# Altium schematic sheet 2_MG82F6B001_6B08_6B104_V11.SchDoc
size A4
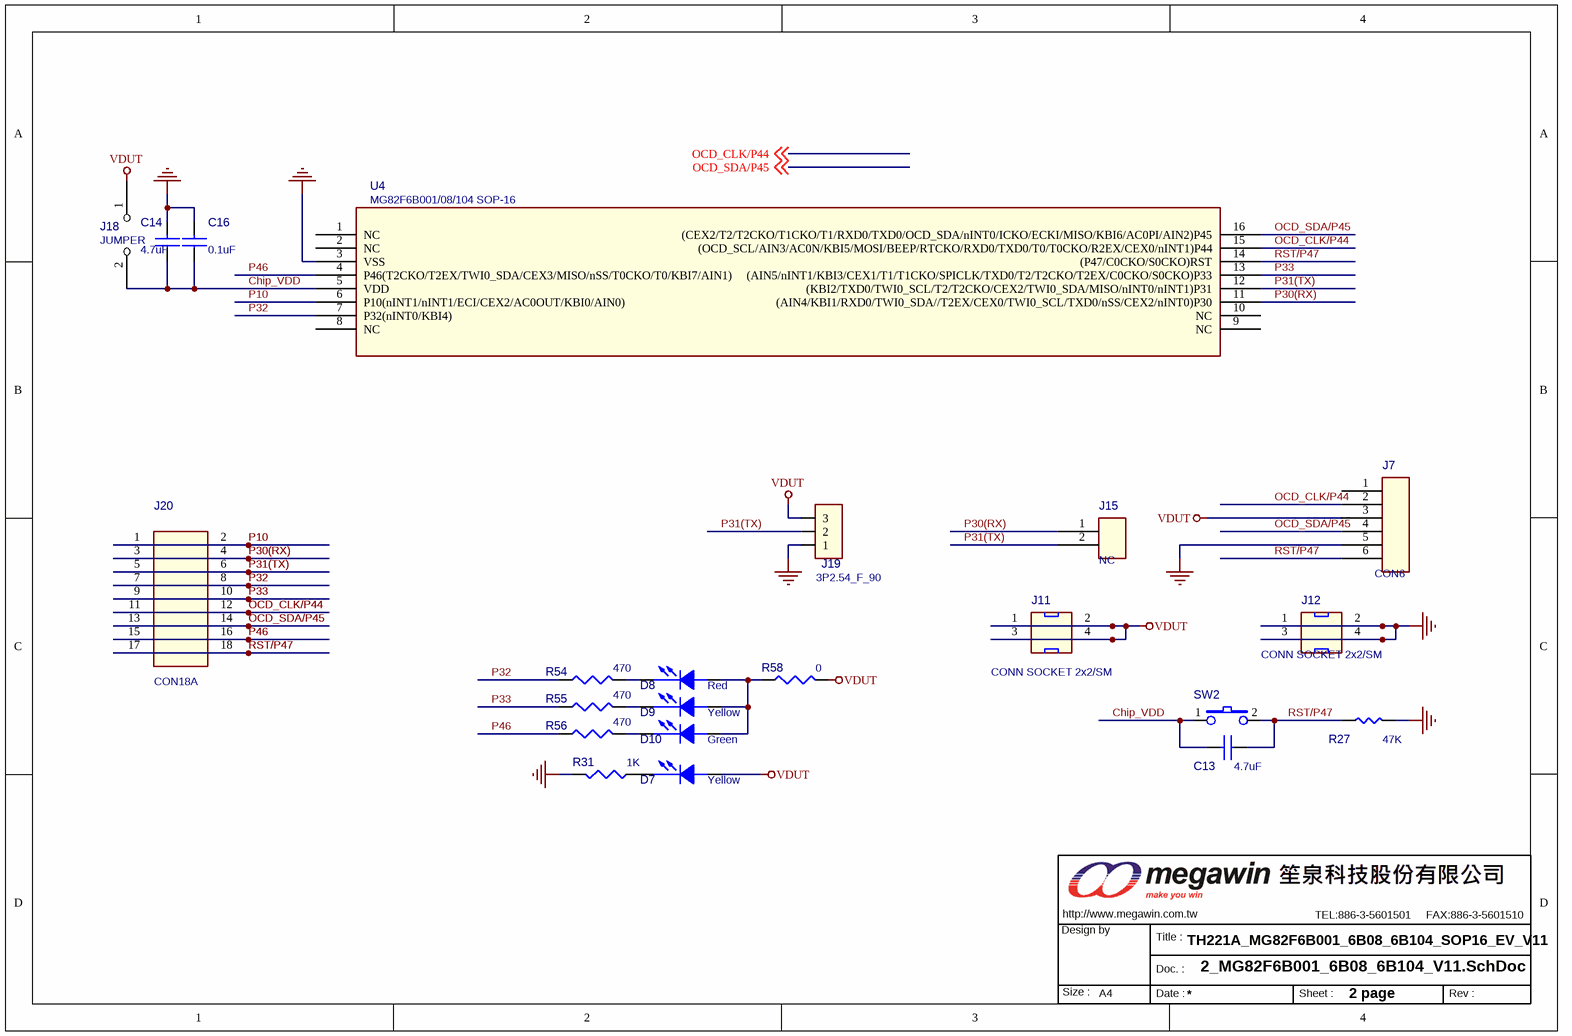
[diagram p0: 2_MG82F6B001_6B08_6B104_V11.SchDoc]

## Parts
C13  4.7uF  [0805C]
C14  4.7uF  [0805C]
C16  0.1uF  [0603C]
D7  Yellow  [0805D]
D8  Red  [LED38+0805]
D9  Yellow  [LED38+0805]
D10  Green  [LED38+0805]
J7  CON6  [PS6P254]
J11  CONN SOCKET 2x2/SM  [PS2X2P254]
J12  CONN SOCKET 2x2/SM  [PS2X2P254]
J15  NC  [PS2P254]
J18  JUMPER  [PS2P254]
J19  3P2.54_F_90  [PS3P254f_90]
J20  CON18A  [PS9X2P254]
MW1  OrgAddr3: TEL:886-3-5601501     FAX:886-3-5601510  [MEGAWIN_3.4]  (hidden comment: MW-A4)  (graphical)
R27  47K  [0603R]
R31  1K  [0603R]
R54  470  [0603R]
R55  470  [0603R]
R56  470  [0603R]
R58  0  [PS2p254+0603]
SW2  SW TACT-SPST  [SW_T_2P]  (value not drawn)
U4  MG82F6B001/08/104 SOP-16  [SO16_150P127]

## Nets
GND_POWER: C14.2 C16.2 J7.5 J12.1 J12.2 J12.3 J12.4 J19.1 R27.2 R31.1 U4.3(VSS)
VDUT: D7.1(ANODE) J7.3 J11.1 J11.2 J11.3 J11.4 J18.1 J19.3 R58.2
Chip_VDD: C13.2 C14.1 C16.1 J18.2 SW2.1 U4.5(VDD)
OCD_CLK/P44: J7.2 J20.11 J20.12 U4.15((OCD_SCL/AIN3/AC0N/KBI5/MOSI/BEEP/RTCKO/RXD0/TXD0/T0/T0CKO/R2EX/CEX0/nINT1)P44) ; off-sheet OCD_CLK/P44
OCD_SDA/P45: J7.4 J20.13 J20.14 U4.16((CEX2/T2/T2CKO/T1CKO/T1/RXD0/TXD0/OCD_SDA/nINT0/ICKO/ECKI/MISO/KBI6/AC0PI/AIN2)P45) ; off-sheet OCD_SDA/P45
P10: J20.1 J20.2 U4.6(P10(nINT1/nINT1/ECI/CEX2/AC0OUT/KBI0/AIN0))
P30(RX): J15.1 J20.3 J20.4 U4.11((AIN4/KBI1/RXD0/TWI0_SDA//T2EX/CEX0/TWI0_SCL/TXD0/nSS/CEX2/nINT0)P30)
P31(TX): J15.2 J19.2 J20.5 J20.6 U4.12((KBI2/TXD0/TWI0_SCL/T2/T2CKO/CEX2/TWI0_SDA/MISO/nINT0/nINT1)P31)
P32: J20.7 J20.8 R54.1 U4.7(P32(nINT0/KBI4))
P33: J20.9 J20.10 R55.1 U4.13((AIN5/nINT1/KBI3/CEX1/T1/T1CKO/SPICLK/TXD0/T2/T2CKO/T2EX/C0CKO/S0CKO)P33)
P46: J20.15 J20.16 R56.1 U4.4(P46(T2CKO/T2EX/TWI0_SDA/CEX3/MISO/nSS/T0CKO/T0/KBI7/AIN1))
RST/P47: C13.1 J7.6 J20.17 J20.18 R27.1 SW2.2 U4.14((P47/C0CKO/S0CKO)RST)
NetD7_2: D7.2(CATHODE) R31.2
NetD8_1: D8.1(ANODE) D9.1(ANODE) D10.1(ANODE) R58.1
NetD8_2: D8.2(CATHODE) R54.2
NetD9_2: D9.2(CATHODE) R55.2
NetD10_2: D10.2(CATHODE) R56.2

Not connected (* = marked no-connect by the designer): J7 1; U4 1(NC) 2(NC) 8(NC) 9(NC) 10(NC)

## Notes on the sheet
- TH221A_MG82F6B001_6B08_6B104_SOP16_EV_V11
- 2 page

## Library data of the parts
C13 C14 C16 = CAP NP_Dup1
D7-D10 = LED
J7 = CON6_Dup1
J15 = CON2
J19 = CON3
MW1 = MW_A4_2
R27 = R_Dup2
R31 R54-R56 R58 = R_Dup3
U4 = MG82F6B001/08/104_SOP-16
